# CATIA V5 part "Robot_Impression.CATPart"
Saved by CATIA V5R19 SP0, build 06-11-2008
Part number: Robot_Impression
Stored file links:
  G:\EU_thinkMotion\CFAO_2010\MMS_groupe3\MMS_groupe3\A reprendre\evulliez\evulliez\Robot_Impression.CATPart

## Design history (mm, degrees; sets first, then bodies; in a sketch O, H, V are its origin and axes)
Parameters
  Lx = 20000 mm
  Ly = 600 mm
  Lz = 4000 mm
  LENGTH = 0 mm
Body1 (main body)
  Point1: (0, 0, 0)
  Line1: type Normal, RefPoint Point1, RefSkin yz-plane, Start -10000 {= -Lx /2}, End 10000 {= Lx /2}
  Line2: type Normal, RefPoint Point1, RefSkin xy-plane, Start -100, End 4000 {= Lz}
  Point2: (0, 0, 2500)
  Line3: type Normal, RefPoint Point2, RefSkin zx-plane, Start -300 {= -Ly /2}, End 300 {= Ly /2}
